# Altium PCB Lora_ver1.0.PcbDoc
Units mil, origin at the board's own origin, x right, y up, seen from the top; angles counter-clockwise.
Board outline 1653.54 x 3149.61 mil, 2 copper layers (Top Layer, Bottom Layer); 29 components, 19 nets, 108 pads, 13 vias.
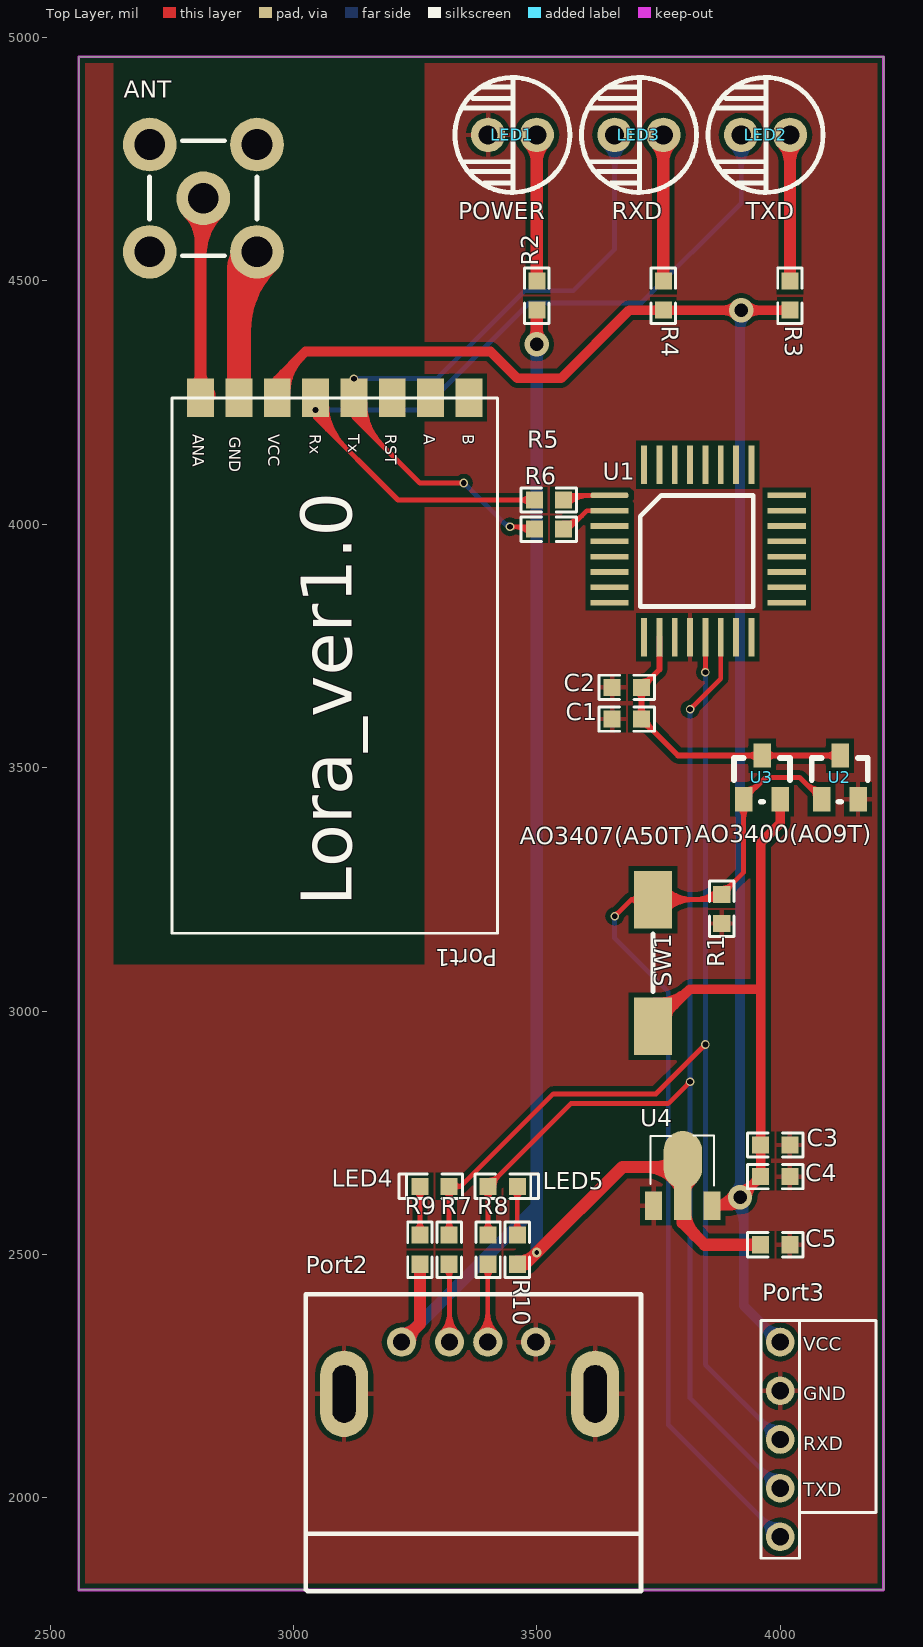
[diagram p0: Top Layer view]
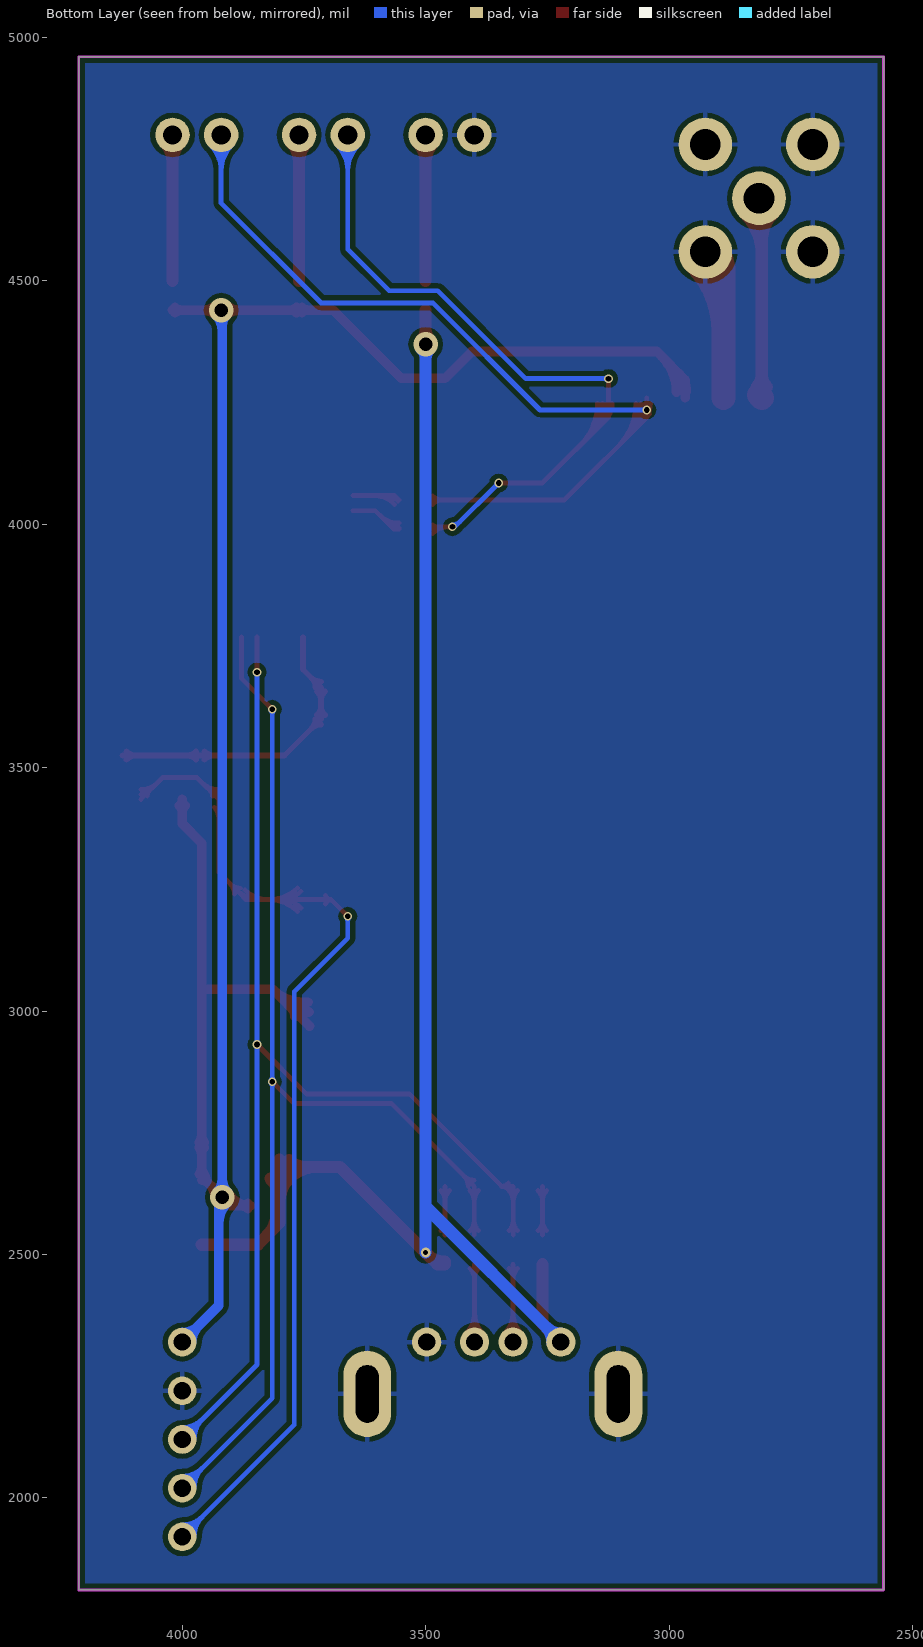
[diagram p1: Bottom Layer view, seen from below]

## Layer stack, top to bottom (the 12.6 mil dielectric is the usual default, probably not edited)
Top Layer: signal copper 1.4
Dielectric: dielectric 12.6, FR-4, Dk 4.8
Bottom Layer: signal copper 1.4

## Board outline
2559.06,1811.02 4212.6,1811.02 4212.6,4960.63 2559.06,4960.63

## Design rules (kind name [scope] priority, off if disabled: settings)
Clearance [All] p1: gap=10
PolygonConnect [All] p1: connectstyle=Relief reliefconductorwidth=10 reliefentries=4 polygonreliefangle="90 Angle"
RoutingVias [All] p1: holewidth=28 width=50 viastyle="Through Hole" minholewidth=8 minwidth=10 maxholewidth=28 maxwidth=50
SilkscreenOverComponentPads [All] p1: minsilkscreentomaskgap=10
SolderMaskExpansion [All] p1: expansion=4
Width [All] p1: maxlimit=50 minlimit=10 preferedwidth=10
27 further rules are at their usual default settings.

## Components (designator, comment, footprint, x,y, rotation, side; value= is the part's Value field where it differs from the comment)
ANT "ANT" SWA-KE天线母座 2815,4670 r0 top
C1 "47uF" 0603 3655,3600 r0 top
C2 "104" 0603 3655,3665 r0 top
C3 "104" 0603 4020,2725 r180 top
C4 "104" 0603 3960,2660 r0 top
C5 "10uF" 0603 3960,2520 r0 top
LED1 "POWER" 2.54LED 3400,4800 r180 top
LED2 "TXD" 2.54LED 3920,4800 r180 top
LED3 "RXD" 2.54LED 3660,4800 r180 top
LED4 "RX" LED-0603 3260,2640 r0 top
LED5 "TX" LED-0603 3460,2640 r180 top
Port1 "Lora" LoRa_Usart 3085,4260 r270 top
Port2 "USB_A" USB-A 3360,2320 r0 top
Port3 "DEBUG" STC_DEBUG 4000,2120 r0 top
R1 "1M" 0603 3880,3180 r90 top
R2 "4.7K" 0603 3500,4500 r270 top
R3 "4.7K" 0603 4020,4500 r270 top
R4 "4.7K" 0603 3760,4500 r270 top
R5 "0R" 0603 3495,4050 r0 top
R6 "0R" 0603 3495,3990 r0 top
R7 "0R" 0603 3320,2480 r90 top
R8 "0R" 0603 3400,2480 r90 top
R9 "4.7K" 0603 3260,2540 r270 top
R10 "4.7K" 0603 3460,2540 r270 top
SW1 "REST" SW-1 3660,3040 r180 top
U1 "STC8F2K32S2" LQPF-32 3685,4095 r0 top
U2 "AO3400(AO9T)" SOT-23 4120,3480 r0 top
U3 "AO3407(A50T)" SOT-23 3960,3480 r0 top
U4 "HT7533-1" 3A5A3D 3800,2600 r0 top

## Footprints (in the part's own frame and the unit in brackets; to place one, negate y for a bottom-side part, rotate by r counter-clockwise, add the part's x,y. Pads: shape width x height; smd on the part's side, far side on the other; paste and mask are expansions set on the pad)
2.54LED [mm]
  round 1.8 hole 1: 1(-2.54,0) 2(0,0)
  silkscreen extent -4.27,-3 1.73,3
3A5A3D [mm]
  rect 0.9x1.5 smd: 1(-1.524,0) 3(1.524,0)
  rect 0.9x1.8 smd: 2(0,0.15)
  oval 2x3 smd: 2(0,2.4)
  silkscreen extent -1.68,1.07 1.63,3.67
0603 [mil]
  rect 35x35 smd: 1(0,0) 2(60,0)
  silkscreen extent -27,-25 87,25
LED-0603 [mil]
  rect 35x35 smd: 1(0,0) 2(60,0)
  silkscreen extent -43,-25 87,25
LoRa_Usart [mm]
  rect 2x1.397 smd: 1(0,7) 2(0,5) 3(0,3) 4(0,1) 5(0,-1) 6(0,-3) 7(0,-5) 8(0,-7)
  silkscreen extent 0,-8.5 27.94,8.5
LQPF-32 [mm]
  oct 2x0.3 smd: 1(-0.9,-0.9)
  rect 2x0.3 smd: 2(-0.9,-1.7) 3(-0.9,-2.5) 4(-0.9,-3.3) 5(-0.9,-4.1) 6(-0.9,-4.9) 7(-0.9,-5.7) 8(-0.9,-6.5) 17(8.35,-6.5) 18(8.35,-5.7) 19(8.35,-4.9) 20(8.35,-4.1) 21(8.35,-3.3) 22(8.35,-2.5) 23(8.35,-1.7) 24(8.35,-0.9)
  rect 0.3x2 smd: 9(0.9,-8.3) 10(1.7,-8.3) 11(2.5,-8.3) 12(3.3,-8.3) 13(4.1,-8.3) 14(4.9,-8.3) 15(5.7,-8.3) 16(6.5,-8.3) 25(6.5,0.7) 26(5.7,0.7) 27(4.9,0.7) 28(4.1,0.7) 29(3.3,0.7) 30(2.5,0.7) 31(1.7,0.7) 32(0.9,0.7)
  silkscreen extent 0.7,-6.7 6.6,-0.9
SOT-23 [mil]
  rect 36x50 smd: 1(40,-45) 2(-35,-45) 3(3,45)
  silkscreen extent -55,-50 60,40
STC_DEBUG [mm]
  round 1.5 hole 0.9: 1(0,5.08) 2(0,2.54) 3(0,0) 4(0,-2.54) 5(0,-5.08)
  silkscreen extent -1,-6.2 5,6.2
SW-1 [mm]
  rect 2x3 smd: 1(-2,1.8) 2(-2,-4.8)
  silkscreen extent -2,-3 -2,0
SWA-KE天线母座 [mm]
  round 2.8 hole 1.6: 1(0,0) 2(-2.8,-2.8) 2(-2.8,2.8) 2(2.8,-2.8) 2(2.8,2.8)
  silkscreen extent -2.8,-3 2.8,3
USB-A [mm]
  round 1.524 hole 0.9: 1(-3.5,0) 2(-1,0) 3(1,0) 4(3.5,0)
  oval 2.5x4.5 hole 1.2 slot 3 at 90 deg: 4(-6.5,-2.7) 4(6.6,-2.7)
  silkscreen extent -8.5,-13 9,2.5

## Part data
ANT C1 C2 C3 C4 C5: library part Cap, "Capacitor"
LED1 LED2 LED3 LED4 LED5: library part DIODE, "diode"
Port2: library part USB
Port3: library part PIN-5
R1 R2 R3 R4 R5 R6 R7 R8 R9 R10: library part Res2, "Resistor"
SW1: library part SW-P, "key"
U1: library part STC8F2K64S2
U2: library part MOSFET-N, "mosfet"
U3: library part MOSFET-P, "mosfet"

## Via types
v1: diameter 17.72, hole 11.81, Top Layer to Bottom Layer, 9 vias
v2: diameter 50, hole 28, Top Layer to Bottom Layer, 3 vias
v3: diameter 20, hole 10, Top Layer to Bottom Layer, 1 vias

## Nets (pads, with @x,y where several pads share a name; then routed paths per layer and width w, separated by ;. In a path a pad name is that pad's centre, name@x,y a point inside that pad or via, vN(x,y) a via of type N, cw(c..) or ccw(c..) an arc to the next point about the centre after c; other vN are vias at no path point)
ANT: ANT.1 Port1.8 | length 687.1
  Top Layer w20: ANT.1@2809.41,4664.41 ANT.1
  Top Layer w25: ANT.1@2784.86,4639.86 cw(c2725.61,4580.61) 2809.41,4580.61 ; Port1.8@2798.8,4282.48 ccw(c2773.2,4308.08) 2809.41,4308.08 ccw(c2845.62,4308.08) Port1.8@2820.02,4282.48 ; Port1.8 ANT.1@2809.41,4664.41 ; 2809.41,4553.61 cw(c2931.39,4553.61) ANT.1@2845.14,4639.86 ; 2809.41,4613.97 cw(c2871.03,4613.97) ANT.1@2827.46,4657.54
  Top Layer w50: Port1.8 Port1.8@2815,4265.59
GND: ANT.2 C1.1 C2.1 C3.1 C4.2 C5.2 LED1.2 Port1.7 Port2.4 Port3.2 R1.1 U1.12 U2.1 U4.1 | length 533.4
  Top Layer w50: Port1.7 2888.15,4522.68 ANT.2@2925.24,4559.76 ; 2888.15,4397.52 cw(c3087.48,4397.52) ANT.2@2946.53,4538.47 ; 2888.15,4518.23 cw(c2966.77,4518.23) ANT.2@2911.18,4573.82
LORA-RX: LED3.2 Port1.4 R6.1 | length 2039.4
  Top Layer w10: Port1.4@3116.87,4248.13 ccw(c3165.15,4248.13) 3131.01,4213.99 ; Port1.4@3121.64,4296.64 cw(c3115.06,4290.06) 3124.37,4290.06 cw(c3133.68,4290.06) Port1.4@3127.1,4296.64 ; v1(3124.37,4299.37) Port1.4 3124.37,4220.63 3260,4085 v1(3350,4085) ; Port1.4@3126.87,4248.13 ccw(c3199.3,4248.13) 3148.08,4196.92 ; Port1.4@3136.87,4248.13 ccw(c3233.44,4248.13) 3165.15,4179.85 ; Port1.4@3146.87,4248.13 ccw(c3267.58,4248.13) 3182.23,4162.77 ; v1@3347.27,4082.27 ccw(c3340.69,4075.69) 3340.69,4085 ccw(c3340.69,4094.31) v1@3347.27,4087.73 ; v1(3445,3995) 3490,3995 R6.1 ; v1@3447.73,3992.27 cw(c3454.31,3985.69) 3454.31,3995 cw(c3454.31,4004.31) v1@3447.73,3997.73 ; v1@3452.75,3995 cw(c3452.75,3947.75) R6.1@3486.16,3981.16 ; R6.1@3486.16,3998.84 cw(c3476.89,4008.11) 3476.89,3995 cw(c3476.89,3971.89) R6.1@3493.23,3988.23
  Bottom Layer w10: v1(3124.37,4299.37) 3294.37,4299.37 3475,4480 3575,4480 3660,4565 LED3.2 ; v1@3127.1,4296.64 cw(c3133.68,4290.06) 3133.68,4299.37 cw(c3133.68,4308.68) v1@3127.1,4302.1 ; v1@3350,4081.14 cw(c3350,4071.83) 3356.59,4078.41 cw(c3363.17,4085) v1@3353.86,4085 ; v1(3350,4085) 3440,3995 v1(3445,3995) ; 3429.88,4005.12 ccw(c3445,4020.24) v1@3445,3998.86 ; LED3.2@3638.48,4778.48 cw(c3586.53,4726.53) 3660,4726.53 cw(c3733.47,4726.53) LED3.2@3681.52,4778.48 ; LED3.2@3645.55,4785.55 cw(c3610.67,4750.67) 3660,4750.67 cw(c3709.33,4750.67) LED3.2@3674.45,4785.55
LORA-TX: LED2.2 Port1.5 R5.1 | length 2298.4
  Top Layer w10: Port1.5@3038.13,4248.13 ccw(c3089.46,4248.13) 3053.16,4211.84 ; Port1.5@3040.22,4226.29 cw(c3038.5,4219.37) 3045.63,4219.37 ; Port1.5@3042.9,4237.73 ccw(c3036.32,4244.31) 3045.63,4244.31 ccw(c3054.94,4244.31) Port1.5@3048.36,4237.73 ; v1(3045.63,4235) Port1.5 ; Port1.5@3048.13,4248.13 ccw(c3123.6,4248.13) 3070.23,4194.77 ; Port1.5@3051.04,4226.29 ccw(c3052.76,4219.37) 3045.63,4219.37 ; Port1.5@3058.13,4248.13 ccw(c3157.74,4248.13) 3087.3,4177.69 ; Port1.5@3068.13,4248.13 ccw(c3191.88,4248.13) 3104.38,4160.62 ; R5.1@3486.16,4041.16 ccw(c3464.82,4019.82) 3464.82,4050 ccw(c3464.82,4080.18) R5.1@3486.16,4058.84 ; R5.1 3215,4050 3045.63,4219.37
  Bottom Layer w10: v1(3045.63,4235) 3265,4235 3485,4455 3715,4455 3920,4660 LED2.2 ; v1@3048.36,4232.27 cw(c3054.94,4225.69) 3054.94,4235 cw(c3054.94,4244.31) v1@3048.36,4237.73 ; LED2.2@3898.48,4778.48 cw(c3846.53,4726.53) 3920,4726.53 cw(c3993.47,4726.53) LED2.2@3941.52,4778.48 ; LED2.2@3905.55,4785.55 cw(c3870.67,4750.67) 3920,4750.67 cw(c3969.33,4750.67) LED2.2@3934.45,4785.55
NetLED1_1: LED1.1 R2.1 | length 387
  Top Layer w25: LED1.1@3483.78,4783.78 cw(c3444.63,4744.63) 3500,4744.63 cw(c3555.37,4744.63) LED1.1@3516.22,4783.78 ; R2.1 LED1.1
NetLED2_1: LED2.1 R3.1 | length 387
  Top Layer w25: LED2.1@4003.78,4783.78 cw(c3964.63,4744.63) 4020,4744.63 cw(c4075.37,4744.63) LED2.1@4036.22,4783.78 ; R3.1 LED2.1
NetLED3_1: LED3.1 R4.1 | length 387
  Top Layer w25: LED3.1@3743.78,4783.78 cw(c3704.63,4744.63) 3760,4744.63 cw(c3815.37,4744.63) LED3.1@3776.22,4783.78 ; R4.1 LED3.1
NetLED4_1: LED4.1 R9.1 | length 194.8
  Top Layer w10: R9.1@3251.16,2548.84 ccw(c3229.82,2570.18) 3260,2570.18 ccw(c3290.18,2570.18) R9.1@3268.84,2548.84 ; LED4.1@3251.16,2631.16 cw(c3229.82,2609.82) 3260,2609.82 cw(c3290.18,2609.82) LED4.1@3268.84,2631.16 ; R9.1 LED4.1
NetLED5_1: LED5.1 R10.1 | length 194.8
  Top Layer w10: R10.1@3451.16,2548.84 ccw(c3429.82,2570.18) 3460,2570.18 ccw(c3490.18,2570.18) R10.1@3468.84,2548.84 ; LED5.1@3451.16,2631.16 cw(c3429.82,2609.82) 3460,2609.82 cw(c3490.18,2609.82) LED5.1@3468.84,2631.16 ; R10.1 LED5.1
NetPort2_2: Port2.2 R7.1 | length 359.4
  Top Layer w10: Port2.2@3302.95,2337.68 ccw(c3260.27,2380.36) 3320.63,2380.36 ccw(c3380.99,2380.36) Port2.2@3338.31,2337.68 ; Port2.2@3310.02,2330.61 ccw(c3284.42,2356.21) 3320.63,2356.21 ccw(c3356.84,2356.21) Port2.2@3331.24,2330.61 ; R7.1@3311.16,2471.16 cw(c3288.3,2448.3) 3320.63,2448.3 ; R7.1 3320.63,2479.37 Port2.2 ; 3320.63,2451.34 cw(c3348.66,2451.34) R7.1@3328.84,2471.16
NetPort2_3: Port2.3 R8.1 | length 359.4
  Top Layer w10: Port2.3@3381.69,2337.68 ccw(c3339.01,2380.36) 3399.37,2380.36 ccw(c3459.73,2380.36) Port2.3@3417.05,2337.68 ; Port2.3@3388.76,2330.61 ccw(c3363.16,2356.21) 3399.37,2356.21 ccw(c3435.58,2356.21) Port2.3@3409.98,2330.61 ; R8.1@3391.16,2471.16 cw(c3371.34,2451.34) 3399.37,2451.34 ; Port2.3 3399.37,2479.37 R8.1 ; 3399.37,2448.3 cw(c3431.7,2448.3) R8.1@3408.84,2471.16
P10: R5.2 U1.1 | length 178.3
  Top Layer w10: R5.2 3564.57,4059.57 U1.1 ; R5.2@3556.77,4048.23 cw(c3584.13,4020.87) 3584.13,4059.57 ; R5.2@3563.84,4041.16 cw(c3608.27,3996.73) 3608.27,4059.57
P11: R6.2 U1.2 | length 176.7
  Top Layer w10: R6.2 3565,3990 3603.07,4028.07 U1.2 ; R6.2@3555,3992.5 ccw(c3555,4022.68) 3576.34,4001.34 ; R6.2@3555,4002.5 ccw(c3555,4056.82) 3593.41,4018.41
RXD: LED4.2 Port3.3 R7.2 U1.13 | length 2806.7
  Top Layer w10: R7.2@3311.16,2548.84 ccw(c3289.82,2570.18) 3320,2570.18 ccw(c3350.18,2570.18) R7.2@3328.84,2548.84 ; LED4.2@3311.16,2631.16 cw(c3289.82,2609.82) 3320,2609.82 cw(c3350.18,2609.82) LED4.2@3328.84,2631.16 ; R7.2 LED4.2 3343.79,2640 ; LED4.2@3330.29,2632.91 cw(c3343.79,2623.62) 3343.79,2640 ; LED4.2@3330.29,2647.09 ccw(c3343.79,2656.38) 3343.79,2640 ; v1@3842.56,2931.42 cw(c3833.24,2931.42) 3839.83,2924.83 cw(c3846.42,2918.24) v1@3846.42,2927.56 ; v1@3843.69,3699.15 ccw(c3837.1,3705.73) 3846.42,3705.73 ccw(c3855.73,3705.73) v1@3849.15,3699.15 ; v1(3846.42,2931.42) 3745,2830 3533.79,2830 3343.79,2640 ; v1(3846.42,3696.42) U1.13
  Bottom Layer w10: v1@3843.69,2928.69 cw(c3837.1,2922.1) 3846.42,2922.1 cw(c3855.73,2922.1) v1@3849.15,2928.69 ; v1@3843.69,2934.15 ccw(c3837.1,2940.73) 3846.42,2940.73 ccw(c3855.73,2940.73) v1@3849.15,2934.15 ; v1@3843.69,3693.69 cw(c3837.1,3687.1) 3846.42,3687.1 cw(c3855.73,3687.1) v1@3849.15,3693.69 ; v1(3846.42,3696.42) 3846.42,2935 v1(3846.42,2931.42) 3846.42,2273.58 Port3.3 ; Port3.3@3975.47,2120 ccw(c3916.26,2120) 3958.13,2161.87 ccw(c4000,2203.74) Port3.3@4000,2144.53 ; Port3.3@3985.47,2120 ccw(c3950.4,2120) 3975.2,2144.8 ccw(c4000,2169.6) Port3.3@4000,2134.53
TRG: Port3.5 R1.2 SW1.2 U2.2 U3.2 | length 2817.6
  Top Layer w10: v1(3660,3195) 3693.98,3228.98 ; v1@3660,3198.86 ccw(c3660,3208.17) 3666.59,3201.59 ccw(c3673.17,3195) v1@3663.86,3195 ; SW1.2@3705.54,3220.1 ccw(c3693.98,3217.01) 3693.98,3228.98 ; SW1.2@3705.54,3237.85 cw(c3693.98,3240.94) 3693.98,3228.98 ; SW1.2@3755.97,3211.74 cw(c3797.57,3170.14) 3797.57,3228.98 cw(c3797.57,3287.81) SW1.2@3755.97,3246.21 ; SW1.2@3763.04,3204.67 cw(c3821.72,3146) 3821.72,3228.98 cw(c3821.72,3311.95) SW1.2@3763.04,3253.28 ; 3823.21,3228.98 ccw(c3823.21,3296.79) R1.2@3871.16,3248.84 ; 3847.35,3228.98 ccw(c3847.35,3272.65) R1.2@3878.23,3241.77 ; R1.2@3880,3252.5 ccw(c3880,3282.68) 3901.34,3261.34 ccw(c3922.68,3240) R1.2@3892.5,3240 ; U3.2@3915.81,3418.81 cw(c3893.62,3396.62) 3925,3396.62 cw(c3956.38,3396.62) U3.2@3934.19,3418.81 ; U3.2@3925,3445 ccw(c3925,3469.14) U3.2@3942.07,3452.07 ; U3.2@3925,3455 ccw(c3925,3503.28) 3959.14,3469.14 ; U3.2@3938,3442 cw(c3952.49,3442) U3.2@3942.24,3452.24 ; 4050.86,3469.14 ccw(c4085,3503.28) U2.2@4085,3455 ; U2.2@4067.76,3452.24 cw(c4057.51,3442) U2.2@4072,3442 ; U2.2@4067.93,3452.07 ccw(c4085,3469.14) U2.2@4085,3445 ; U2.2 4040,3480 3970,3480 U3.2 3925,3285 R1.2 3868.98,3228.98 SW1.2 3693.98,3228.98
  Bottom Layer w10: v1@3657.27,3192.27 cw(c3650.69,3185.69) 3660,3185.69 cw(c3669.31,3185.69) v1@3662.73,3192.27 ; v1(3660,3195) 3660,3150 3770,3040 3770,2150 Port3.5 ; Port3.5@3975.47,1920 ccw(c3916.26,1920) 3958.13,1961.87 ccw(c4000,2003.74) Port3.5@4000,1944.53 ; Port3.5@3985.47,1920 ccw(c3950.4,1920) 3975.2,1944.8 ccw(c4000,1969.6) Port3.5@4000,1934.53
TXD: LED5.2 Port3.4 R8.2 U1.14 | length 2818.4
  Top Layer w10: R8.2@3391.16,2548.84 ccw(c3369.82,2570.18) 3400,2570.18 ccw(c3430.18,2570.18) R8.2@3408.84,2548.84 ; LED5.2@3391.16,2631.16 cw(c3369.82,2609.82) 3400,2609.82 cw(c3430.18,2609.82) LED5.2@3408.84,2631.16 ; R8.2 LED5.2 3570,2810 3770,2810 v1(3815,2855) ; LED5.2@3400,2652.5 ccw(c3400,2682.68) 3421.34,2661.34 ccw(c3442.68,2640) LED5.2@3412.5,2640 ; v1@3811.14,2855 cw(c3801.83,2855) 3808.41,2848.41 cw(c3815,2841.83) v1@3815,2851.14 ; v1(3815,3620) 3877.91,3682.91 U1.14 ; v1@3815,3623.86 ccw(c3815,3633.17) 3821.59,3626.59 ccw(c3828.17,3620) v1@3818.86,3620
  Bottom Layer w10: v1@3812.27,2852.27 cw(c3805.69,2845.69) 3815,2845.69 cw(c3824.31,2845.69) v1@3817.73,2852.27 ; v1@3812.27,2857.73 ccw(c3805.69,2864.31) 3815,2864.31 ccw(c3824.31,2864.31) v1@3817.73,2857.73 ; v1@3812.27,3617.27 cw(c3805.69,3610.69) 3815,3610.69 cw(c3824.31,3610.69) v1@3817.73,3617.27 ; v1(3815,3620) 3815,2205 Port3.4 ; Port3.4@3975.47,2020 ccw(c3916.26,2020) 3958.13,2061.87 ccw(c4000,2103.74) Port3.4@4000,2044.53 ; Port3.4@3985.47,2020 ccw(c3950.4,2020) 3975.2,2044.8 ccw(c4000,2069.6) Port3.4@4000,2034.53
VCC: C3.2 C4.1 Port1.6 Port3.1 R3.2 R4.2 SW1.1 U3.1 U4.3 | length 5613.1
  Top Layer w20: Port1.6@2964.39,4271.87 cw(c3018.76,4271.87) 2980.31,4310.31 ; Port1.6 2966.89,4296.89 3025,4355 3405,4355 3460,4300 3550,4300 3690,4440 R4.2 3780,4440 v2(3920,4440) R3.2 ; Port1.6@2984.39,4271.87 cw(c3087.04,4271.87) 3014.46,4344.46 ; SW1.1 3814.61,3045 ; SW1.1@3739.52,2998.16 ccw(c3744.19,3054.41) 3784.1,3014.49 ; SW1.1@3741.17,3018.09 ccw(c3748.87,3110.73) 3814.6,3045 ; R4.2@3754.7,4434.7 ccw(c3741.89,4421.89) 3741.89,4440 ccw(c3741.89,4458.11) R4.2@3754.7,4445.3 ; SW1.1@3768.11,2988.82 cw(c3791.49,2988.82) SW1.1@3774.96,3005.35 ; U4.3@3865.46,2594.54 cw(c3878.63,2581.37) 3878.63,2600 cw(c3878.63,2618.63) U4.3@3865.46,2605.46 ; 3895.31,2600 ccw(c3895.31,2631.06) v2@3921.95,2615.09 ; v2@3904.79,2625.37 cw(c3860,2652.22) U4.3 3900,2600 v2(3917.66,2617.66) C4.1 3960,2720 C3.2 3960,3045 ; v2@3909.39,4429.39 ccw(c3883.79,4403.79) 3883.79,4440 ccw(c3883.79,4476.21) v2@3909.39,4450.61 ; v2@3917.66,2632.66 ccw(c3917.66,2668.87) 3943.27,2643.27 ccw(c3968.87,2617.66) v2@3932.66,2617.66 ; v2@3930.61,4429.39 cw(c3956.21,4403.79) 3956.21,4440 cw(c3956.21,4476.21) v2@3930.61,4450.61 ; C4.1@3952.5,2660 cw(c3934.39,2660) 3947.2,2647.2 cw(c3960,2634.39) C4.1@3960,2652.5 ; C4.1@3954.7,2665.3 ccw(c3941.89,2678.11) 3960,2678.11 ccw(c3978.11,2678.11) C4.1@3965.3,2665.3 ; C3.2@3954.7,2719.7 cw(c3941.89,2706.89) 3960,2706.89 cw(c3978.11,2706.89) C3.2@3965.3,2719.7 ; C3.2@3954.7,2730.3 ccw(c3941.89,2743.11) 3960,2743.11 ccw(c3978.11,2743.11) C3.2@3965.3,2730.3 ; U3.1@3994.34,3422.34 cw(c3980.69,3408.69) 4000,3408.69 cw(c4019.31,3408.69) U3.1@4005.66,3422.34 ; U3.1 4000,3385 3960,3345 3960,3045 ; R3.2@4014.7,4434.7 ccw(c4001.89,4421.89) 4001.89,4440 ccw(c4001.89,4458.11) R3.2@4014.7,4445.3 ; R4.2@3765.3,4434.7 cw(c3778.11,4421.89) 3778.11,4440 ; R4.2@3765.3,4434.7 cw(c3778.11,4421.89) 3778.11,4440 ; R4.2@3765.3,4434.7 cw(c3778.11,4421.89) 3778.11,4440 ; R4.2@3765.3,4445.3 ccw(c3778.11,4458.11) 3778.11,4440 ; R4.2@3765.3,4445.3 ccw(c3778.11,4458.11) 3778.11,4440 ; R4.2@3765.3,4445.3 ccw(c3778.11,4458.11) 3778.11,4440 ; 3814.61,3045 3960,3045
  Bottom Layer w20: v2@3907.05,2607.05 cw(c3863.72,2563.72) 3925,2563.72 ; v2@3907.05,2628.27 ccw(c3881.45,2653.87) 3917.66,2653.87 ccw(c3953.87,2653.87) v2@3928.27,2628.27 ; v2@3909.39,4429.39 cw(c3889.44,4409.44) 3917.66,4409.44 ; 3917.66,4398.13 cw(c3961.87,4398.13) v2@3930.61,4429.39 ; v2(3920,4440) 3917.66,4437.66 v2(3917.66,2617.66) 3925,2625 3925,2395 Port3.1 ; Port3.1@3980.47,2320 ccw(c3933.33,2320) 3966.66,2353.34 ccw(c4000,2386.67) Port3.1@4000,2339.53
VCC_5V: C5.1 Port2.1 R2.2 R9.2 R10.2 U4.2 | length 3761.3
  Top Layer w25: Port2.1 3260,2357.8 R9.2 ; Port2.1@3222.2,2337.5 ccw(c3222.2,2379.75) 3252.08,2349.87 ccw(c3281.95,2320) Port2.1@3239.7,2320 ; R10.2 3476.06,2480 v3(3500,2503.94) 3676.06,2680 U4.2@3800,2680 ; R10.2@3460,2485 ccw(c3460,2535.85) v3@3495.96,2499.89 ; v2@3491.16,4378.92 ccw(c3469.82,4400.26) 3500,4400.26 ccw(c3530.18,4400.26) v2@3508.84,4378.92 ; v2(3500,4370.08) R2.2 ; 3722.58,2680 cw(c3722.58,2597.39) 3781,2655.8 cw(c3735.13,2609.93) 3800,2609.93 cw(c3864.87,2609.93) U4.2@3819,2655.8 ; 3747.68,2680 ccw(c3747.68,2727.13) U4.2@3781,2693.8 ; U4.2@3800,2694.49 U4.2@3800,2680 ; U4.2@3805.22,2588.19 ccw(c3873.79,2588.19) 3825.3,2539.7 ; C5.1 3845,2520 3800,2565 3800,2605.91 U4.2@3800,2680
  Bottom Layer w25: Port2.1 3222.2,2320.63 3500,2598.43 ; Port2.1@3222.2,2337.5 ccw(c3222.2,2378.23) 3251,2349.43 ; Port2.1@3239.7,2320 cw(c3283.47,2320) 3252.52,2350.95 ; v2@3491.16,4361.24 cw(c3469.82,4339.9) 3500,4339.9 cw(c3530.18,4339.9) v2@3508.84,4361.24 ; v3(3500,2503.94) 3500,2598.43 ; v2(3500,4370.08) 3500,2598.43
VCORE: C1.2 C2.2 U1.10 U2.3 U3.3 | length 933.6
  Top Layer w12: C1.2@3706.87,3608.13 ccw(c3687.24,3627.76) 3715,3627.76 ccw(c3742.76,3627.76) C1.2@3723.13,3608.13 ; C2.2@3706.87,3656.87 cw(c3687.24,3637.24) 3715,3637.24 cw(c3742.76,3637.24) C2.2@3723.13,3656.87 ; C1.2@3715,3588.5 cw(c3715,3560.74) 3734.63,3580.37 cw(c3754.26,3600) C1.2@3726.5,3600 ; C2.2@3715,3676.5 ccw(c3715,3704.26) 3734.63,3684.63 ccw(c3754.26,3665) C2.2@3726.5,3665 ; U1.10 3751.93,3701.93 C2.2 C1.2 3790,3525 U3.3 4000,3525 U2.3 ; U3.3@3954.51,3516.51 ccw(c3934.03,3496.03) 3934.03,3525 ccw(c3934.03,3553.97) U3.3@3954.51,3533.49 ; U3.3@3971.49,3516.51 cw(c3991.97,3496.03) 3991.97,3525 cw(c3991.97,3553.97) U3.3@3971.49,3533.49 ; U2.3@4114.51,3516.51 ccw(c4094.03,3496.03) 4094.03,3525 ccw(c4094.03,3553.97) U2.3@4114.51,3533.49
pads on no net: Port1.1 Port1.2 Port1.3 U1.3 U1.4 U1.5 U1.6 U1.7 U1.8 U1.9 U1.11 U1.15 U1.16 U1.17 U1.18 U1.19 U1.20 U1.21 U1.22 U1.23 U1.24 U1.25 U1.26 U1.27 U1.28 U1.29 U1.30 U1.31 U1.32

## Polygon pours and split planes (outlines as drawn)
GND on Bottom Layer "Bottom Layer-No Net" (solid, remove dead copper): 2170,5260 2355,5075 2355,1645 5170,1645 5180,1655 4835,2000 4835,5105
GND on Top Layer "Bottom Layer-No Net" (solid, remove dead copper): 2130,5215 2130,1600 2140,1590 2180,1630 4465,1630 4465,5170 4555,5260

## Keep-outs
Keep-Out Layer:
  the board outline again, w6

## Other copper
Top Layer:
  pour cut-out: 2630,4960.63 2630,3095 3270,3095 3270,4955.63 3265,4960.63

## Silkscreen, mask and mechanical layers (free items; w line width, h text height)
Top Overlay:
  text "Lora_ver1.0" at 3155,3215 h180 r90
